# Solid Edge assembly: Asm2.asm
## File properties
Author: Deepak Maini
Template: Normal.asm
Last saved by: CADCIM
Revision: 11
Application: Solid Edge
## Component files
Part1.par
Part2.par
Part3.par
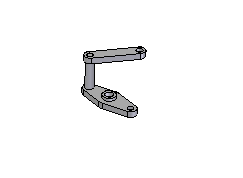
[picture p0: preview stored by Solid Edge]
